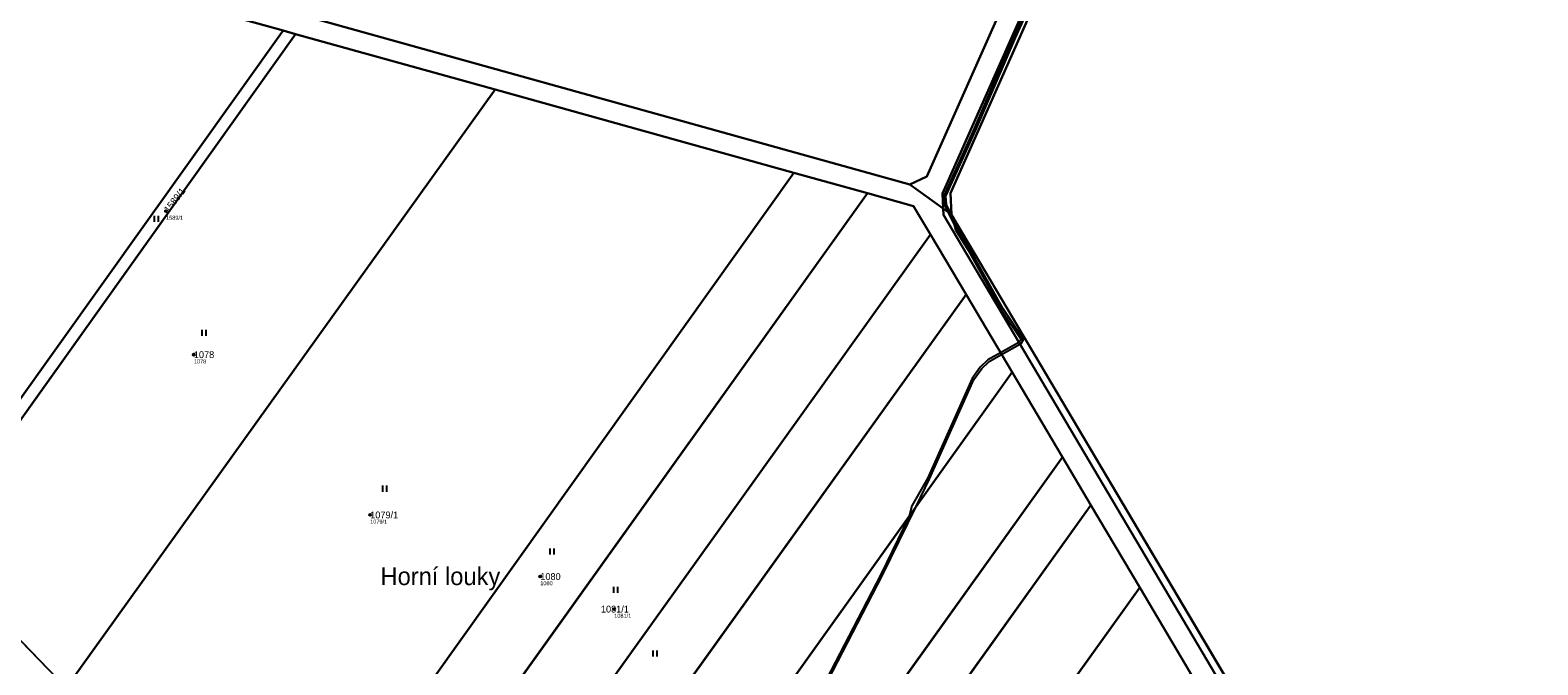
# Model space of a CAD drawing. Extents: x -658203 to -653176, y -1156738 to -1151709.
# Drawn here: x -655015.7 to -654641.1, y -1153355.8 to -1153198.1 of the extents above; entities that cross this region are included whole.
import ezdxf

# ---------------------------------------------------------------- set-up
doc = ezdxf.new("R2010")
doc.units = 0
for name, color, linetype in [('Vrstva 1', 7, 'Continuous'), ('Vrstva 13', 7, 'Continuous'), ('Vrstva 2', 7, 'Continuous'), ('Vrstva 3', 7, 'Continuous'), ('Vrstva 50', 7, 'Continuous'), ('Vrstva 51', 7, 'Continuous'), ('Vrstva 7', 7, 'Continuous')]:
    doc.layers.add(name, color=color, linetype=linetype)

msp = doc.modelspace()

# ---------------------------------------------------------------- linework, layer by layer
at = {"layer": 'Vrstva 1'}
for p, q in [((-654797.13, -1153236.48), (-654947.85, -1153194.5)), ((-655042.87, -1153324.23), (-654952.85, -1153198.23)), ((-654949.76, -1153199.08), (-655040.64, -1153326.53)), ((-654952.85, -1153198.23), (-654949.76, -1153199.08)), ((-654949.76, -1153199.08), (-654900.19, -1153212.88)), ((-654900.19, -1153212.88), (-655006.73, -1153361.56)), ((-654825.97, -1153233.53), (-654900.19, -1153212.88)), ((-654956.68, -1153416.87), (-654825.97, -1153233.53)), ((-654825.97, -1153233.53), (-654807.68, -1153238.62)), ((-654788.89, -1153242.43), (-654797.13, -1153236.48)), ((-654944.82, -1153430.4), (-654807.68, -1153238.62)), ((-654786.83, -1153243.92), (-654788.89, -1153242.43)), ((-654660.71, -1153456.75), (-654786.83, -1153243.92)), ((-654792.04, -1153248.86), (-654888, -1153382.96)), ((-654792.04, -1153248.86), (-654783.17, -1153263.83)), ((-654921.62, -1153456.87), (-654783.17, -1153263.83)), ((-654783.17, -1153263.83), (-654771.75, -1153283.1)), ((-654907.45, -1153473.03), (-654771.75, -1153283.1)), ((-654771.75, -1153283.1), (-654759.21, -1153304.26)), ((-654882.85, -1153476.97), (-654759.21, -1153304.26)), ((-654759.21, -1153304.26), (-654752.17, -1153316.13)), ((-654863.81, -1153472.07), (-654752.17, -1153316.13)), ((-654752.17, -1153316.13), (-654740.04, -1153336.61)), ((-655006.73, -1153361.56), (-655040.64, -1153326.53)), ((-654841.65, -1153478.29), (-654740.04, -1153336.61)), ((-654740.04, -1153336.61), (-654727.4, -1153357.94))]:
    msp.add_line(p, q, dxfattribs=at)
for points in [[(-654797.13, -1153236.48), (-654792.97, -1153234.5), (-654687.83, -1152997.81), (-654689.31, -1152993.76)], [(-654682, -1152997.01), (-654789.07, -1153238.69), (-654788.89, -1153242.43)], [(-654786.83, -1153243.92), (-654787.08, -1153238.6), (-654680.17, -1152997.82)], [(-655017.72, -1153175.16), (-654995.78, -1153186.28), (-654952.85, -1153198.23)], [(-654807.68, -1153238.62), (-654796.22, -1153241.81), (-654792.04, -1153248.86)], [(-654651.11, -1153476.87), (-654788.82, -1153244.01), (-654788.89, -1153242.43)]]:
    msp.add_lwpolyline(points, dxfattribs=at)
at = {"layer": 'Vrstva 13'}
for points in [[(-654755.77, -1153165.21), (-654771.4, -1153199.86), (-654781.15, -1153222.52), (-654788.73, -1153239.24), (-654788.54, -1153241.54), (-654787.68, -1153243.31), (-654786.14, -1153246.46), (-654785.79, -1153247.7), (-654782.69, -1153252.76), (-654774.37, -1153267.66), (-654769.51, -1153275.01), (-654770.07, -1153275.72), (-654774.61, -1153278.27), (-654777.76, -1153280.04), (-654779.68, -1153281.85), (-654781.67, -1153284.67), (-654792.69, -1153309.36), (-654796.7, -1153316.32), (-654797.33, -1153318.9), (-654804.35, -1153333.34), (-654817.96, -1153359.59)], [(-654817.52, -1153359.83), (-654803.91, -1153333.56), (-654795.62, -1153316.51), (-654792.25, -1153309.58), (-654781.23, -1153284.91), (-654779.3, -1153282.19), (-654777.46, -1153280.44), (-654774.36, -1153278.7), (-654769.81, -1153276.15), (-654769.54, -1153276), (-654768.91, -1153275.01), (-654773.95, -1153267.4), (-654782.27, -1153252.5), (-654785.33, -1153247.5), (-654785.68, -1153246.28), (-654786.83, -1153243.92), (-654788.04, -1153241.4), (-654788.23, -1153239.32), (-654780.69, -1153222.7), (-654770.94, -1153200.04), (-654755.33, -1153165.47)]]:
    msp.add_lwpolyline(points, dxfattribs=at)
at = {"layer": 'Vrstva 3'}
for p, q in [((-654984.79, -1153245.71), (-654984.79, -1153244.21)), ((-654983.79, -1153245.71), (-654983.79, -1153244.21)), ((-654972.94, -1153274.08), (-654972.94, -1153272.58)), ((-654971.94, -1153274.08), (-654971.94, -1153272.58)), ((-654928.09, -1153312.8), (-654928.09, -1153311.3)), ((-654927.09, -1153312.8), (-654927.09, -1153311.3)), ((-654886.49, -1153328.39), (-654886.49, -1153326.89)), ((-654885.49, -1153328.39), (-654885.49, -1153326.89)), ((-654870.69, -1153337.92), (-654870.69, -1153336.42)), ((-654869.69, -1153337.92), (-654869.69, -1153336.42)), ((-654860.93, -1153353.73), (-654860.93, -1153352.23)), ((-654859.93, -1153353.73), (-654859.93, -1153352.23))]:
    msp.add_line(p, q, dxfattribs=at)
at = {"layer": 'Vrstva 50'}
for centre in [(-654981.95, -1153243.07), (-654975.04, -1153278.75), (-654931.23, -1153318.58), (-654888.97, -1153333.89), (-654870.6, -1153341.98)]:
    msp.add_circle(centre, 0.25, dxfattribs=at)
at = {"layer": 'Vrstva 51'}
for points in [[(-654830.75, -1152930.92), (-654947.85, -1153194.5), (-654797.13, -1153236.48), (-654792.97, -1153234.5), (-654687.83, -1152997.81), (-654689.31, -1152993.76)], [(-654797.13, -1153236.48), (-654788.89, -1153242.43), (-654789.07, -1153238.69), (-654682, -1152997.01), (-654689.31, -1152993.76), (-654687.83, -1152997.81), (-654792.97, -1153234.5)], [(-654680.17, -1152997.82), (-654682, -1152997.01), (-654789.07, -1153238.69), (-654788.89, -1153242.43), (-654786.83, -1153243.92), (-654787.08, -1153238.6)], [(-654660.71, -1153456.75), (-654493.53, -1153080.78), (-654680.17, -1152997.82), (-654787.08, -1153238.6), (-654786.83, -1153243.92)], [(-654952.85, -1153198.23), (-654995.78, -1153186.28), (-655017.72, -1153175.16), (-655092.98, -1153280.45), (-655062.68, -1153303.83), (-655042.87, -1153324.23)], [(-654949.76, -1153199.08), (-654952.85, -1153198.23), (-655042.87, -1153324.23), (-655040.64, -1153326.53)], [(-655040.64, -1153326.53), (-655006.73, -1153361.56), (-654900.19, -1153212.88), (-654949.76, -1153199.08)], [(-654956.68, -1153416.87), (-654825.97, -1153233.53), (-654900.19, -1153212.88), (-655006.73, -1153361.56), (-654990.09, -1153378.75)], [(-654944.82, -1153430.4), (-654807.68, -1153238.62), (-654825.97, -1153233.53), (-654956.68, -1153416.87)], [(-654792.04, -1153248.86), (-654796.22, -1153241.81), (-654807.68, -1153238.62), (-654944.82, -1153430.4), (-654935.04, -1153441.55), (-654933.96, -1153441.61), (-654930.76, -1153438.7), (-654928.74, -1153436.26), (-654927.01, -1153428.34), (-654923.25, -1153420.56), (-654902.41, -1153397.71), (-654888, -1153382.96)], [(-654649.34, -1153475.94), (-654660.71, -1153456.75), (-654786.83, -1153243.92), (-654788.89, -1153242.43), (-654788.82, -1153244.01), (-654651.11, -1153476.87), (-654622.15, -1153540.74), (-654565.1, -1153666.54), (-654564.72, -1153662.39), (-654595.83, -1153594.23), (-654599.2, -1153586.41), (-654604.03, -1153576.53), (-654618.34, -1153544.74), (-654620.87, -1153539.11)], [(-654932.23, -1153444.76), (-654921.62, -1153456.87), (-654783.17, -1153263.83), (-654792.04, -1153248.86), (-654888, -1153382.96)], [(-654771.75, -1153283.1), (-654783.17, -1153263.83), (-654921.62, -1153456.87), (-654907.45, -1153473.03)], [(-654882.85, -1153476.97), (-654759.21, -1153304.26), (-654771.75, -1153283.1), (-654907.45, -1153473.03), (-654899.54, -1153481.26), (-654892.36, -1153490.25)], [(-654863.81, -1153472.07), (-654752.17, -1153316.13), (-654759.21, -1153304.26), (-654882.85, -1153476.97)], [(-654740.04, -1153336.61), (-654752.17, -1153316.13), (-654863.81, -1153472.07), (-654860.61, -1153471.25), (-654856.33, -1153470.29), (-654852.09, -1153470.22), (-654848.07, -1153471.27), (-654845.01, -1153474), (-654841.65, -1153478.29)], [(-654827.08, -1153497.21), (-654727.4, -1153357.94), (-654740.04, -1153336.61), (-654841.65, -1153478.29), (-654837.68, -1153483.36)]]:
    msp.add_lwpolyline(points, close=True, dxfattribs=at)
for points in [[(-654622.15, -1153540.74), (-654651.11, -1153476.87), (-654788.82, -1153244.01), (-654788.89, -1153242.43), (-654797.13, -1153236.48), (-654947.85, -1153194.5), (-654950.74, -1153193.69), (-654993.98, -1153181.65), (-655121.74, -1153116.8), (-655172.46, -1153091.06), (-655194.75, -1153084.31), (-655240.87, -1153070.34)], [(-655243.21, -1153074.58), (-655174.47, -1153095.66), (-655140.94, -1153112.66), (-655119.54, -1153123.52), (-655044.11, -1153161.77), (-655017.72, -1153175.16), (-654995.78, -1153186.28), (-654952.85, -1153198.23), (-654949.76, -1153199.08), (-654900.19, -1153212.88), (-654825.97, -1153233.53), (-654807.68, -1153238.62), (-654796.22, -1153241.81), (-654792.04, -1153248.86)], [(-654792.04, -1153248.86), (-654783.17, -1153263.83), (-654771.75, -1153283.1), (-654759.21, -1153304.26), (-654752.17, -1153316.13)], [(-654752.17, -1153316.13), (-654740.04, -1153336.61), (-654727.4, -1153357.94), (-654719.85, -1153370.67), (-654705.12, -1153395.53), (-654690.84, -1153419.62), (-654685.39, -1153428.82), (-654680.87, -1153436.44), (-654672, -1153451.41), (-654655.54, -1153479.19), (-654654.14, -1153482.29), (-654653.66, -1153483.33), (-654648.22, -1153495.35), (-654636.53, -1153521.16)], [(-655006.73, -1153361.56), (-655040.64, -1153326.53)]]:
    msp.add_lwpolyline(points, dxfattribs=at)

# ---------------------------------------------------------------- texts
at = {"layer": 'Vrstva 2'}
msp.add_text('1589/1', height=1.7, rotation=52, dxfattribs=at).set_placement((-654981.28, -1153243.59))
for s, p in [('1078', (-654975.04, -1153279.6)), ('1079/1', (-654931.23, -1153319.43)), ('1080', (-654888.97, -1153334.74)), ('1081/1', (-654873.91, -1153342.83))]:
    msp.add_text(s, height=1.7, dxfattribs=at).set_placement(p)
at = {"layer": 'Vrstva 50'}
for s, p in [('1589/1', (-654981.95, -1153245.23)), ('1078', (-654975.04, -1153280.91)), ('1079/1', (-654931.23, -1153320.74)), ('1080', (-654888.97, -1153336.05)), ('1081/1', (-654870.6, -1153344.14))]:
    msp.add_text(s, height=1, dxfattribs=at).set_placement(p)
at = {"layer": 'Vrstva 7'}
msp.add_text('Horní louky', height=4.4, dxfattribs=at).set_placement((-654928.67, -1153336.02))

doc.saveas('drawing.dxf')
